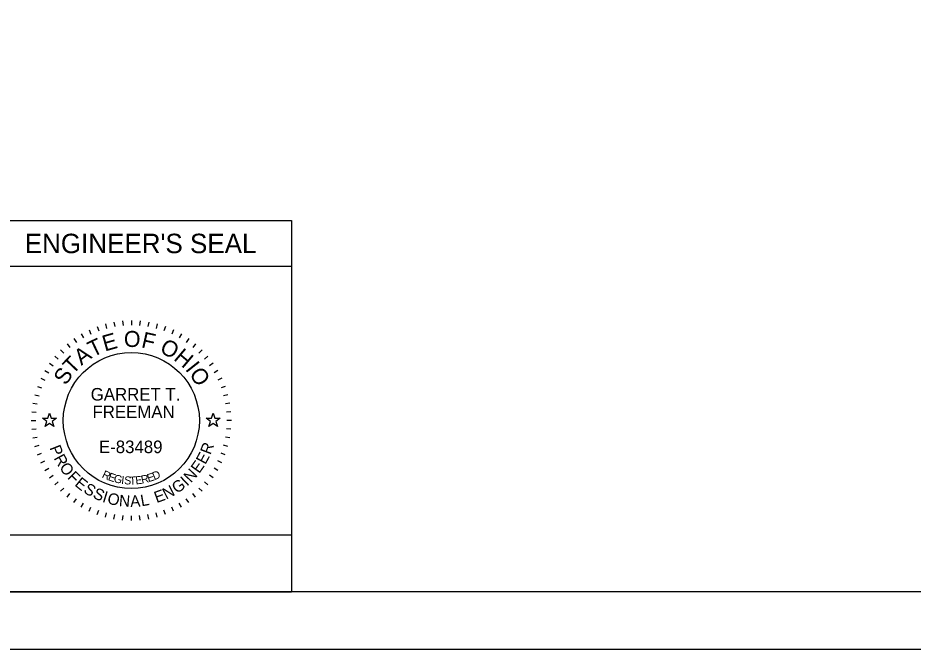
# Model space of a CAD drawing. Extents: x 0 to 48.6, y 0 to 22.
# Drawn here: x 24.01 to 31.84, y 0 to 5.52 of the extents above; entities that cross this region are included whole.
import ezdxf

# ---------------------------------------------------------------- set-up
doc = ezdxf.new("R2010")
doc.units = 0
for name, color, linetype in [('SH_Border', 7, 'Continuous'), ('SH_Cut_Line', 7, 'Continuous'), ('SH_Data', 7, 'Continuous'), ('SH_Seal', 7, 'Continuous')]:
    doc.layers.add(name, color=color, linetype=linetype)

msp = doc.modelspace()

# ---------------------------------------------------------------- linework, layer by layer
at = {"layer": 'SH_Border'}
msp.add_lwpolyline([(1.5, 21.5), (33.5, 21.5), (33.5, 0.5), (1.5, 0.5)], close=True, dxfattribs=at)
at = {"layer": 'SH_Cut_Line'}
msp.add_lwpolyline([(0, 0), (34, 0), (34, 22), (0, 22)], close=True, dxfattribs=at)
at = {"layer": 'SH_Data'}
for p, q in [((23.6, 3.75), (26.4, 3.75)), ((26.4, 3.75), (26.4, 0.5)), ((23.6, 3.35), (26.4, 3.35)), ((23.6, 0.5), (26.4, 0.5))]:
    msp.add_line(p, q, dxfattribs=at)
msp.add_lwpolyline([(23.6, 0.5), (23.6, 1), (26.4, 1), (26.4, 0.5)], close=True, dxfattribs=at)
at = {"layer": 'SH_Seal'}
for p, q in [((24.7007, 2.8222), (24.7144, 2.7846)), ((24.7735, 2.8452), (24.7839, 2.8065)), ((24.8481, 2.8617), (24.855, 2.8223)), ((24.9237, 2.8717), (24.9272, 2.8318)), ((25, 2.875), (25, 2.835)), ((25.0763, 2.8717), (25.0728, 2.8318)), ((25.1519, 2.8617), (25.145, 2.8223)), ((25.2265, 2.8452), (25.2161, 2.8065)), ((25.2993, 2.8222), (25.2856, 2.7846)), ((24.5625, 2.7578), (24.5825, 2.7231)), ((24.6302, 2.793), (24.6471, 2.7568)), ((25.3698, 2.793), (25.3529, 2.7568)), ((25.4375, 2.7578), (25.4175, 2.7231)), ((24.4376, 2.6703), (24.4633, 2.6396)), ((24.4981, 2.7168), (24.5211, 2.684)), ((25.5019, 2.7168), (25.4789, 2.684)), ((25.5624, 2.6703), (25.5367, 2.6396)), ((24.3813, 2.6187), (24.4096, 2.5904)), ((25.6187, 2.6187), (25.5904, 2.5904)), ((24.3297, 2.5624), (24.3604, 2.5367)), ((25.6703, 2.5624), (25.6396, 2.5367)), ((24.2422, 2.4375), (24.2769, 2.4175)), ((24.2832, 2.5019), (24.316, 2.4789)), ((25.7168, 2.5019), (25.684, 2.4789)), ((25.7578, 2.4375), (25.7231, 2.4175)), ((24.207, 2.3698), (24.2432, 2.3529)), ((25.793, 2.3698), (25.7568, 2.3529)), ((24.1778, 2.2993), (24.2154, 2.2856)), ((25.8222, 2.2993), (25.7846, 2.2856)), ((24.1548, 2.2265), (24.1935, 2.2161)), ((25.8452, 2.2265), (25.8065, 2.2161)), ((24.1383, 2.1519), (24.1777, 2.145)), ((25.8617, 2.1519), (25.8223, 2.145)), ((24.1283, 2.0763), (24.1682, 2.0728)), ((25.8717, 2.0763), (25.8318, 2.0728)), ((24.125, 2), (24.165, 2)), ((25.875, 2), (25.835, 2)), ((24.1283, 1.9237), (24.1682, 1.9272)), ((25.8717, 1.9237), (25.8318, 1.9272)), ((24.1383, 1.8481), (24.1777, 1.855)), ((25.8617, 1.8481), (25.8223, 1.855)), ((24.1548, 1.7735), (24.1935, 1.7839)), ((25.8452, 1.7735), (25.8065, 1.7839)), ((24.1778, 1.7007), (24.2154, 1.7144)), ((24.207, 1.6302), (24.2432, 1.6471)), ((25.793, 1.6302), (25.7568, 1.6471)), ((25.8222, 1.7007), (25.7846, 1.7144)), ((24.2422, 1.5625), (24.2769, 1.5825)), ((25.7578, 1.5625), (25.7231, 1.5825)), ((24.2832, 1.4981), (24.316, 1.5211)), ((25.7168, 1.4981), (25.684, 1.5211)), ((24.3297, 1.4376), (24.3604, 1.4633)), ((24.3813, 1.3813), (24.4096, 1.4096)), ((25.6187, 1.3813), (25.5904, 1.4096)), ((25.6703, 1.4376), (25.6396, 1.4633)), ((24.4376, 1.3297), (24.4633, 1.3604)), ((25.5624, 1.3297), (25.5367, 1.3604)), ((24.4981, 1.2832), (24.5211, 1.316)), ((24.5625, 1.2422), (24.5825, 1.2769)), ((25.4375, 1.2422), (25.4175, 1.2769)), ((25.5019, 1.2832), (25.4789, 1.316)), ((24.6302, 1.207), (24.6471, 1.2432)), ((24.7007, 1.1778), (24.7144, 1.2154)), ((24.7735, 1.1548), (24.7839, 1.1935)), ((24.8481, 1.1383), (24.855, 1.1777)), ((25.1519, 1.1383), (25.145, 1.1777)), ((25.2265, 1.1548), (25.2161, 1.1935)), ((25.2993, 1.1778), (25.2856, 1.2154)), ((25.3698, 1.207), (25.3529, 1.2432)), ((24.9237, 1.1283), (24.9272, 1.1682)), ((25, 1.125), (25, 1.165)), ((25.0763, 1.1283), (25.0728, 1.1682))]:
    msp.add_line(p, q, dxfattribs=at)
for points in [[(24.2236, 2.02), (24.2705, 2.02), (24.285, 2.0645), (24.2995, 2.02), (24.3464, 2.02), (24.3085, 1.9924), (24.323, 1.9478), (24.285, 1.9754), (24.247, 1.9478), (24.2615, 1.9924)], [(25.6536, 2.02), (25.7005, 2.02), (25.715, 2.0645), (25.7295, 2.02), (25.7764, 2.02), (25.7385, 1.9924), (25.753, 1.9478), (25.715, 1.9754), (25.677, 1.9478), (25.6915, 1.9924)]]:
    msp.add_lwpolyline(points, close=True, dxfattribs=at)
msp.add_circle((25, 2), 0.595, dxfattribs=at)

# ---------------------------------------------------------------- texts
at = {"layer": 'SH_Data'}
msp.add_text("ENGINEER'S SEAL", height=0.17, dxfattribs=at).set_placement((24.0676, 3.465))
at = {"layer": 'SH_Seal'}
for s, height, rotation, p in [('E', 0.14, 15.75706, (24.7684, 2.6038)), ('O', 0.14, 359.78119, (24.9347, 2.6443)), ('F', 0.14, 347.43619, (25.0811, 2.6417)), ('T', 0.14, 25.71674, (24.6616, 2.5518)), ('O', 0.14, 332.25863, (25.2398, 2.6015)), ('A', 0.14, 36.47472, (24.5634, 2.4781)), ('H', 0.14, 319.91363, (25.3632, 2.5361)), ('T', 0.14, 46.4344, (24.4883, 2.3964)), ('I', 0.14, 308.36695, (25.4665, 2.4483)), ('S', 0.14, 57.19238, (24.4281, 2.3014)), ('O', 0.14, 303.14906, (25.5021, 2.4089)), ('R', 0.1, 69.23216, (25.6919, 1.6954)), ('P', 0.1, 291.49398, (24.2823, 1.7621)), ('E', 0.1, 61.99508, (25.6476, 1.6098)), ('R', 0.1, 298.73106, (24.319, 1.6717)), ('E', 0.1, 54.75801, (25.5933, 1.5314)), ('O', 0.1, 306.46664, (24.3655, 1.5883)), ('N', 0.1, 47.02243, (25.5202, 1.4508)), ('F', 0.1, 314.7068, (24.4343, 1.4983)), ('E', 0.1, 321.43929, (24.4978, 1.4348)), ('R', 0.07, 334.48695, (24.7375, 1.5051)), ('E', 0.07, 341.03996, (24.7906, 1.4801)), ('G', 0.07, 347.47515, (24.8414, 1.4618)), ('I', 0.07, 353.78581, (24.9091, 1.4468)), ('S', 0.07, 356.89262, (24.9358, 1.4429)), ('T', 0.07, 3.00609, (24.9857, 1.4387)), ('E', 0.07, 6.01169, (25.0389, 1.4412)), ('R', 0.07, 11.91844, (25.0925, 1.4474)), ('E', 0.07, 17.68363, (25.1498, 1.4602)), ('D', 0.07, 23.30524, (25.201, 1.477)), ('I', 0.1, 43.28703, (25.4868, 1.4214)), ('S', 0.1, 328.67637, (24.5743, 1.3752)), ('N', 0.1, 27.31129, (25.3045, 1.3075)), ('G', 0.1, 35.04687, (25.3981, 1.357)), ('S', 0.1, 335.91345, (24.6564, 1.3266)), ('I', 0.1, 343.15053, (24.7406, 1.2897)), ('O', 0.1, 346.88592, (24.7839, 1.2751)), ('N', 0.1, 355.12608, (24.8888, 1.2517)), ('A', 0.1, 2.86166, (24.9923, 1.2437)), ('L', 0.1, 10.09874, (25.0894, 1.249)), ('E', 0.1, 20.07421, (25.2212, 1.277))]:
    msp.add_text(s, height=height, rotation=rotation, dxfattribs=at).set_placement(p)
for s, p in [('GARRET T.', (24.6446, 2.1749)), ('FREEMAN', (24.66, 2.0216)), ('E-83489', (24.7166, 1.7151))]:
    msp.add_text(s, height=0.11, dxfattribs=at).set_placement(p)

doc.saveas('drawing.dxf')
